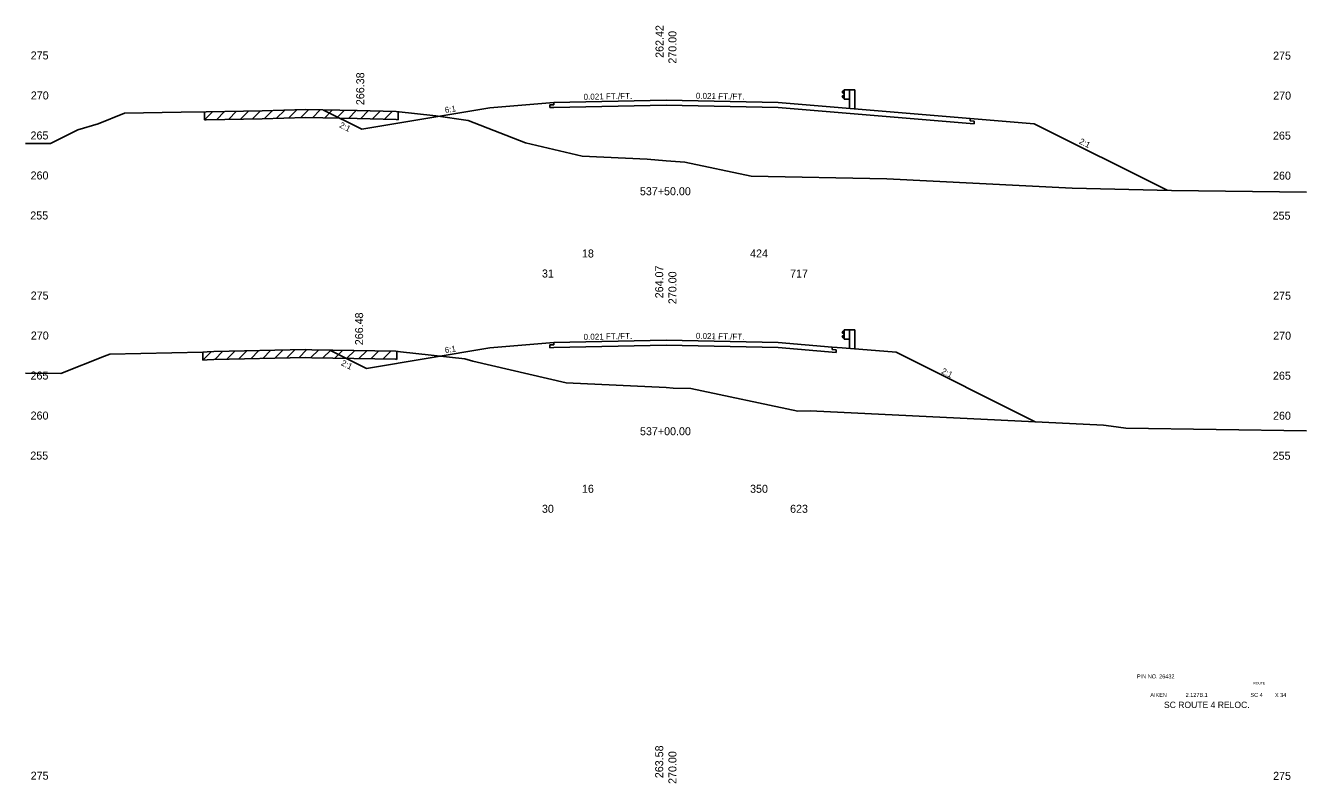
# Model space of a CAD drawing. Extents: x 2967 to 4323, y -3677 to -817.
# Drawn here: x 3555.3 to 3715.3, y -2670.2 to -2575.5 of the extents above; entities that cross this region are included whole.
import ezdxf

# ---------------------------------------------------------------- set-up
doc = ezdxf.new("R2010")
doc.units = 0
for name, color, linetype in [('Level 1', 7, 'Continuous'), ('Level 10', 7, 'Continuous'), ('Level 11', 7, 'Continuous'), ('Level 12', 7, 'Continuous'), ('Level 20', 7, 'Continuous'), ('Level 24', 7, 'Continuous'), ('Level 3', 7, 'Continuous'), ('Level 32', 7, 'Continuous'), ('Level 33', 7, 'Continuous'), ('Level 59', 7, 'Continuous'), ('Level 6', 7, 'Continuous'), ('Level 60', 7, 'Continuous'), ('Level 61', 7, 'Continuous'), ('Level 7', 7, 'Continuous')]:
    doc.layers.add(name, color=color, linetype=linetype)

msp = doc.modelspace()

# ---------------------------------------------------------------- linework, layer by layer
at = {"layer": 'Level 11'}
for p, q in [((3621.35, -2585.43), (3620.85, -2585.44)), ((3620.85, -2585.44), (3620.85, -2585.78)), ((3621.35, -2585.13), (3621.35, -2585.43)), ((3620.85, -2585.78), (3621.35, -2585.77)), ((3649.35, -2585.77), (3673.85, -2587.81)), ((3673.35, -2587.43), (3673.35, -2587.13)), ((3673.35, -2587.43), (3673.85, -2587.47)), ((3673.85, -2587.81), (3673.85, -2587.47)), ((3621.35, -2615.43), (3620.85, -2615.44)), ((3620.85, -2615.44), (3620.85, -2615.78)), ((3620.85, -2615.78), (3621.35, -2615.77)), ((3621.35, -2615.13), (3621.35, -2615.43)), ((3656.1, -2616), (3656.1, -2615.7)), ((3656.6, -2616.38), (3656.6, -2616.04))]:
    msp.add_line(p, q, dxfattribs=at)
at = {"layer": 'Level 12'}
for p, q in [((3635.35, -2585.48), (3621.35, -2585.77)), ((3649.35, -2585.77), (3635.35, -2585.48)), ((3635.35, -2615.48), (3621.35, -2615.77)), ((3649.35, -2615.77), (3635.35, -2615.48)), ((3649.35, -2615.77), (3656.6, -2616.38)), ((3656.1, -2616), (3656.6, -2616.04))]:
    msp.add_line(p, q, dxfattribs=at)
at = {"layer": 'Level 24'}
for p, q in [((3657.62, -2583.62), (3657.35, -2583.82)), ((3657.35, -2583.82), (3657.35, -2583.87)), ((3657.35, -2583.87), (3657.62, -2584.07)), ((3657.62, -2584.72), (3657.62, -2583.55)), ((3657.62, -2583.55), (3658.28, -2583.55)), ((3658.28, -2583.55), (3658.28, -2585.88)), ((3658.28, -2583.55), (3658.95, -2583.55)), ((3658.95, -2583.55), (3658.95, -2585.93)), ((3657.35, -2584.39), (3657.62, -2584.19)), ((3657.35, -2584.44), (3657.35, -2584.39)), ((3657.62, -2584.64), (3657.35, -2584.44)), ((3657.62, -2584.72), (3658.29, -2584.72)), ((3657.62, -2613.62), (3657.35, -2613.82)), ((3657.35, -2613.82), (3657.35, -2613.87)), ((3657.35, -2613.87), (3657.62, -2614.07)), ((3657.35, -2614.39), (3657.62, -2614.19)), ((3657.35, -2614.44), (3657.35, -2614.39)), ((3657.62, -2614.72), (3657.62, -2613.55)), ((3657.62, -2613.55), (3658.28, -2613.55)), ((3658.28, -2613.55), (3658.28, -2615.88)), ((3658.28, -2613.55), (3658.95, -2613.55)), ((3658.95, -2613.55), (3658.95, -2615.93)), ((3657.62, -2614.64), (3657.35, -2614.44)), ((3657.62, -2614.72), (3658.29, -2614.72))]:
    msp.add_line(p, q, dxfattribs=at)
at = {"layer": 'Level 59'}
for p, q in [((3621.35, -2585.13), (3635.35, -2584.84)), ((3635.35, -2584.84), (3649.35, -2585.13)), ((3649.35, -2585.13), (3673.35, -2587.13)), ((3621.35, -2615.13), (3635.35, -2614.84)), ((3635.35, -2614.84), (3649.35, -2615.13)), ((3649.35, -2615.13), (3656.1, -2615.7))]:
    msp.add_line(p, q, dxfattribs=at)
at = {"layer": 'Level 6'}
for p, q in [((3613.35, -2585.8), (3621.35, -2585.13)), ((3673.35, -2587.13), (3681.35, -2587.8)), ((3613.35, -2615.8), (3621.35, -2615.13)), ((3656.1, -2615.7), (3657.35, -2615.8)), ((3657.35, -2615.8), (3664.09, -2616.36))]:
    msp.add_line(p, q, dxfattribs=at)
at = {"layer": 'Level 60'}
for p, q in [((3564.41, -2587.79), (3567.72, -2586.48)), ((3567.72, -2586.48), (3574.79, -2586.34)), ((3574.79, -2586.34), (3577.92, -2586.32)), ((3577.92, -2586.32), (3584.9, -2586.17)), ((3584.9, -2586.17), (3590.33, -2586.03)), ((3590.33, -2586.03), (3596.76, -2586.16)), ((3596.76, -2586.16), (3601.63, -2586.27)), ((3601.63, -2586.27), (3606.58, -2586.8)), ((3606.58, -2586.8), (3610.64, -2587.39)), ((3558.46, -2590.27), (3561.86, -2588.57)), ((3561.86, -2588.57), (3564.41, -2587.79)), ((3610.64, -2587.39), (3617.79, -2590.2)), ((3555.35, -2590.25), (3558.46, -2590.27)), ((3617.79, -2590.2), (3624.86, -2591.84)), ((3624.86, -2591.84), (3633.01, -2592.24)), ((3633.01, -2592.24), (3635.35, -2592.42)), ((3635.35, -2592.42), (3637.7, -2592.6)), ((3637.7, -2592.6), (3645.98, -2594.34)), ((3645.98, -2594.34), (3662.93, -2594.68)), ((3662.93, -2594.68), (3686.1, -2595.83)), ((3686.1, -2595.83), (3698.51, -2596.12)), ((3698.51, -2596.12), (3715.35, -2596.36)), ((3559.76, -2619), (3565.19, -2616.83)), ((3565.19, -2616.83), (3565.86, -2616.58)), ((3565.86, -2616.58), (3577.49, -2616.35)), ((3577.49, -2616.35), (3578.02, -2616.28)), ((3578.02, -2616.28), (3578.88, -2616.26)), ((3578.88, -2616.26), (3590.3, -2616.01)), ((3590.3, -2616.01), (3591.09, -2616.03)), ((3591.09, -2616.03), (3601.58, -2616.23)), ((3601.58, -2616.23), (3602.17, -2616.3)), ((3602.17, -2616.3), (3610.22, -2617.16)), ((3610.22, -2617.16), (3611.22, -2617.46)), ((3611.22, -2617.46), (3622.86, -2620.18)), ((3555.35, -2618.97), (3559.76, -2619)), ((3622.86, -2620.18), (3635.35, -2620.77)), ((3635.35, -2620.77), (3636.25, -2620.82)), ((3636.25, -2620.82), (3638.45, -2620.89)), ((3638.45, -2620.89), (3651.83, -2623.71)), ((3651.83, -2623.71), (3653.37, -2623.69)), ((3653.37, -2623.69), (3690.02, -2625.48)), ((3690.02, -2625.48), (3690.94, -2625.57)), ((3690.94, -2625.57), (3692.78, -2625.85)), ((3692.78, -2625.85), (3715.35, -2626.18))]:
    msp.add_line(p, q, dxfattribs=at)
at = {"layer": 'Level 61'}
for p, q in [((3578.7, -2586.3), (3577.68, -2587.32)), ((3577.68, -2586.32), (3577.68, -2587.32)), ((3577.92, -2587.32), (3584.9, -2587.17)), ((3580.2, -2586.27), (3579.18, -2587.29)), ((3581.7, -2586.24), (3580.68, -2587.26)), ((3583.2, -2586.21), (3582.18, -2587.23)), ((3584.7, -2586.17), (3583.68, -2587.2)), ((3584.9, -2587.17), (3590.33, -2587.03)), ((3586.21, -2586.14), (3585.18, -2587.16)), ((3587.71, -2586.1), (3586.68, -2587.12)), ((3589.21, -2586.06), (3588.18, -2587.09)), ((3590.69, -2586.04), (3589.68, -2587.05)), ((3590.33, -2587.03), (3596.76, -2587.16)), ((3592.16, -2586.07), (3591.18, -2587.05)), ((3593.66, -2586.1), (3592.68, -2587.08)), ((3595.16, -2586.13), (3594.18, -2587.11)), ((3596.66, -2586.16), (3595.68, -2587.14)), ((3596.76, -2587.16), (3601.63, -2587.27)), ((3598.16, -2586.19), (3597.18, -2587.17)), ((3599.66, -2586.23), (3598.68, -2587.2)), ((3601.16, -2586.26), (3600.18, -2587.24)), ((3601.87, -2587.3), (3601.87, -2586.3)), ((3577.68, -2587.32), (3577.92, -2587.32)), ((3601.63, -2587.27), (3601.87, -2587.3)), ((3578.56, -2616.26), (3577.47, -2617.35)), ((3577.47, -2616.35), (3577.47, -2617.35)), ((3577.47, -2617.35), (3577.49, -2617.35)), ((3577.49, -2617.35), (3578.02, -2617.28)), ((3578.02, -2617.28), (3578.88, -2617.26)), ((3578.88, -2617.26), (3590.3, -2617.01)), ((3580, -2616.23), (3578.97, -2617.25)), ((3581.5, -2616.2), (3580.47, -2617.22)), ((3583, -2616.17), (3581.97, -2617.19)), ((3584.5, -2616.14), (3583.47, -2617.16)), ((3586, -2616.1), (3584.97, -2617.13)), ((3587.5, -2616.07), (3586.47, -2617.09)), ((3589, -2616.04), (3587.97, -2617.06)), ((3590.49, -2616.02), (3589.47, -2617.03)), ((3590.3, -2617.01), (3591.09, -2617.03)), ((3591.96, -2616.04), (3590.97, -2617.02)), ((3591.09, -2617.03), (3601.58, -2617.23)), ((3593.46, -2616.07), (3592.47, -2617.05)), ((3594.96, -2616.1), (3593.97, -2617.08)), ((3596.46, -2616.13), (3595.47, -2617.11)), ((3597.96, -2616.16), (3596.97, -2617.14)), ((3599.46, -2616.19), (3598.47, -2617.17)), ((3600.96, -2616.22), (3599.97, -2617.2)), ((3601.58, -2617.23), (3601.71, -2617.25)), ((3601.71, -2617.25), (3601.71, -2616.25))]:
    msp.add_line(p, q, dxfattribs=at)
at = {"layer": 'Level 7'}
for p, q in [((3592.57, -2586.08), (3597.35, -2588.47)), ((3597.35, -2588.47), (3613.35, -2585.8)), ((3681.35, -2587.8), (3697.97, -2596.11)), ((3597.95, -2618.37), (3613.35, -2615.8)), ((3593.35, -2616.07), (3597.95, -2618.37)), ((3664.09, -2616.36), (3681.48, -2625.06))]:
    msp.add_line(p, q, dxfattribs=at)

# ---------------------------------------------------------------- texts
at = {"layer": 'Level 1'}
for s, p in [('18', (3624.85, -2604.51)), ('424', (3645.85, -2604.51)), ('31', (3619.85, -2607.01)), ('717', (3650.85, -2607.01)), ('16', (3624.85, -2633.91)), ('350', (3645.85, -2633.91)), ('30', (3619.85, -2636.41)), ('623', (3650.85, -2636.41))]:
    msp.add_text(s, height=1, dxfattribs=at).set_placement(p)
at = {"layer": 'Level 10'}
for s, p in [('262.42', (3635.04, -2579.56)), ('264.07', (3635, -2609.61)), ('263.58', (3635, -2669.57))]:
    msp.add_text(s, height=1, rotation=90, dxfattribs=at).set_placement(p)
for s, p in [('537+50.00', (3632.09, -2596.73)), ('537+00.00', (3632.1, -2626.72))]:
    msp.add_text(s, height=1, dxfattribs=at).set_placement(p)
at = {"layer": 'Level 20'}
for s, height, p in [('PIN NO. 26432', 0.5, (3694.19, -2657.11)), ('ROUTE', 0.3, (3708.73, -2657.85)), ('AIKEN', 0.5, (3695.85, -2659.42)), (' 2.127B.1', 0.5, (3700.07, -2659.42)), ('SC 4', 0.5, (3708.36, -2659.42)), ('X 34', 0.5, (3711.42, -2659.43)), ('SC ROUTE 4 RELOC.', 0.8, (3697.56, -2660.81))]:
    msp.add_text(s, height=height, dxfattribs=at).set_placement(p)
at = {"layer": 'Level 3'}
for s, p in [(' 275', (3555.61, -2579.76)), (' 275', (3710.82, -2579.78)), (' 270', (3555.63, -2584.76)), (' 270', (3710.83, -2584.78)), (' 265', (3555.59, -2589.76)), (' 265', (3710.8, -2589.78)), (' 260', (3555.6, -2594.76)), (' 260', (3710.81, -2594.78)), (' 255', (3555.56, -2599.76)), (' 255', (3710.76, -2599.78)), (' 275', (3555.61, -2609.76)), (' 275', (3710.82, -2609.78)), (' 270', (3555.63, -2614.76)), (' 270', (3710.83, -2614.78)), (' 265', (3555.59, -2619.76)), (' 265', (3710.8, -2619.78)), (' 260', (3555.6, -2624.76)), (' 260', (3710.81, -2624.78)), (' 255', (3555.56, -2629.76)), (' 255', (3710.76, -2629.78)), (' 275', (3555.61, -2669.76)), (' 275', (3710.82, -2669.78))]:
    msp.add_text(s, height=1, dxfattribs=at).set_placement(p)
at = {"layer": 'Level 32'}
for s, rotation, p in [('0.021 FT./FT.', 1.1916, (3625.06, -2584.81)), ('0.021 FT./FT.', 358.8084, (3639.07, -2584.67)), ('6:1', 9.4623, (3607.78, -2586.47)), ('2:1', 333.435, (3594.47, -2588.21)), ('2:1', 333.435, (3686.88, -2590.24)), ('0.021 FT./FT.', 1.1916, (3625.06, -2614.81)), ('0.021 FT./FT.', 358.8084, (3639.07, -2614.67)), ('6:1', 9.4623, (3607.78, -2616.47)), ('2:1', 333.435, (3594.69, -2617.93)), ('2:1', 333.435, (3669.68, -2618.95))]:
    msp.add_text(s, height=0.75, rotation=rotation, dxfattribs=at).set_placement(p)
at = {"layer": 'Level 33'}
for s, p in [('266.38', (3597.65, -2585.47)), ('266.48', (3597.51, -2615.47))]:
    msp.add_text(s, height=1, rotation=90, dxfattribs=at).set_placement(p)
at = {"layer": 'Level 59'}
for p in [(3636.65, -2580.66), (3636.65, -2610.71), (3636.65, -2670.66)]:
    msp.add_text(' 270.00', height=1, rotation=90, dxfattribs=at).set_placement(p)

doc.saveas('drawing.dxf')
